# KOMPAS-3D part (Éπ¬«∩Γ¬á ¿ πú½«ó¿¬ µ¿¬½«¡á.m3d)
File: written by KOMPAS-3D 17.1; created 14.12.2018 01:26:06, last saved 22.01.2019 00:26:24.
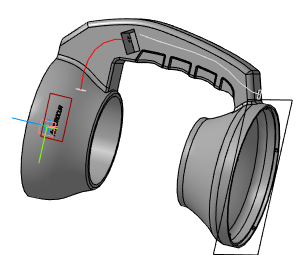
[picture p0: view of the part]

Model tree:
1. Тело  конуса
2. Выдавить тела конуса
     Угол 1 = 360
3. Скруглить грань конуса
     Радиус = 2; Полуось 2 = 1; Коэффициент = 0.5; Хорда = 1
4. Крепежное отверстие
5. Вырезать крепежное отверстие
     Расстояние 1 = 3
6. Копировать отверстия  (with: Вырезать крепежное отверстие)  (6 pattern instances)
     N 1 = 1; Шаг 1 = 10; Шаг 2 = 360; Номер 1 = 1
7. Тело корпуса импеллера
8. Выдавить тело корпуса импеллера
     Угол 1 = 360
9. Полость конуса
10. Вырезать Полость  конуса
     Угол 1 = 360
11. Тело рукоятки
12. Выдавить Тело рукоятки
     Толщина стенки 1 = 1; Расстояние 1 = 15; Расстояние 2 = 15
13. Полость корпуса импеллера
14. Вырезать Полость корпуса импеллера
     Угол 1 = 360
15. Скругление:2
     Радиус = 5
16. Скругление:3
     Радиус = 5
17. Скругление:4
     Радиус = 4
18. Скругление:5
     Радиус = 4
19. Профиль выреза рукоятки (слева)
20. Вырезать Профиль выреза рукоятки (слева)
     Расстояние 1 = 1
21. Скругление:9
     Радиус = 1
22. Скругление:10
     Радиус = 1
23. Скругление:11
     Радиус = 1
24. Скругление:12
     Радиус = 1
25. Профиль выреза рукоятки (срава)
26. Вырезать Профиль выреза рукоятки (срава)
     Расстояние 1 = 1
27. Скругление:33
     Радиус = 1
28. Скругление:34
     Радиус = 1
29. Скругление:35
     Радиус = 1
30. Скругление:36
     Радиус = 1
31. Профиль палечных пазов
32. Вырезать Профиль палечных пазов
     Расстояние 1 = 30
33. Скругление:37
     Радиус = 2
34. Скругление:38
     Радиус = 2
35. Скругление:39
     Радиус = 2
36. Скругление:41
     Радиус = 2
37. Скругление:42
     Радиус = 2
38. Скругление:43
     Радиус = 2
39. Скругление:45
     Радиус = 2
40. Скругление:46
     Радиус = 2
41. Скругление:47
     Радиус = 2
42. Скругление:48
     Радиус = 2
43. Скругление:49
     Радиус = 2
44. Скругление:50
     Радиус = 2
45. Скругление:52
     Радиус = 2
46. Скругление:53
     Радиус = 2
47. Скругление:54
     Радиус = 0.4
48. Скругление:55
     Радиус = 0.4
49. Скругление:56
     Радиус = 0.4
50. Скругление:65
     Радиус = 0.4
51. Соединительный выступ
52. Выдавить Соединительный выступ
     Расстояние 1 = 5
53. Замок воздухоотвода
54. Выдавить Замок воздухоотвода
     Расстояние 1 = 3
55. Плоскость Замоков воздухоотвода
     Расстояние = 187.63
56. Профиль Замоков воздухоотвода
57. Выдавить Замоки воздухоотвода
     Расстояние 1 = 2
58. Профиль кнопки
59. Вырезать Профиль копки
     Расстояние 1 = 25
60. Ось проводки 1.
     Координата Y = -36.91; Координата Z = -22; Координата X = 2; Координата Y = -82; Координата Z = -35; Координата X = 4; Координата Y = -88; Координата Z = -55; Порядок = 4
61. Плоскость профиля проводки
     Расстояние = 36.91
62. Профиль проводки 1.
63. Выдавить Профиль проводки 1.
64. Ось проводки 2.
     Координата X = 4; Координата Y = -94.1501; Координата Z = -61; Координата X = 2; Координата Y = -92; Координата Z = -84; Координата X = 2; Координата Y = -91; Координата Z = -99; Координата X = 2; Координата Y = -90; Координата Z = -115; Координата X = 2; Координата Y = -82; Координата Z = -145; Координата X = 2; Координата Y = -73; Координата Z = -160; Координата X = 2; Координата Y = -68.6906; Координата Z = -176.45; Порядок = 4
65. Плоскость профиля проводки 2.
     Расстояние = 176.45
66. Профиль профодки 2.
67. Выдавить Профиль проводки 2.
68. Плоскость текста
     Расстояние = 64
69. Текст
70. Выдавить текст
     Расстояние 1 = 8.07844; На расстояние 1 = 1
71. Скругление:69  (with: Сечение модели:1)
     Радиус = 3

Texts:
  Точка начала. Х
  Точка начала. Y
  Точка начала. Z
